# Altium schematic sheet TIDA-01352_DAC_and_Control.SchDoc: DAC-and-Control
size 431 x 279 mm; Date: Not shown in title block; ApprovedBy: Not shown in title block; CheckedBy: Not shown in title block; Author: Not shown in title block; CompanyName: Not shown in title block; DrawnBy: Sanjay Pithadia; Engineer: Not shown in title block; Organization: Not shown in title block; Address1: Not shown in title block; Address2: Not shown in title block; Address3: Not shown in title block; Address4: Not shown in title block; DocumentNumber: 1; Revision: Use project parameter SCH_Rev; SheetNumber: 5; SheetTotal: 9; PageSetup: Record=PageOptions¦CenterHorizontal=True¦CenterVertical=True¦PrintScale=1.00¦XCorrection=1.00¦YCorrection=1.00¦PrintKind=0¦BorderSize=5000000¦LeftOffset=0¦BottomOffset=0¦Orientation=2¦PaperLength=1000¦PaperWidth=1000¦Scale=100¦PaperSource=15¦PrintQuality=600¦MediaType=1¦DitherType=10¦PaperKind=Letter¦PrintScaleMode=1
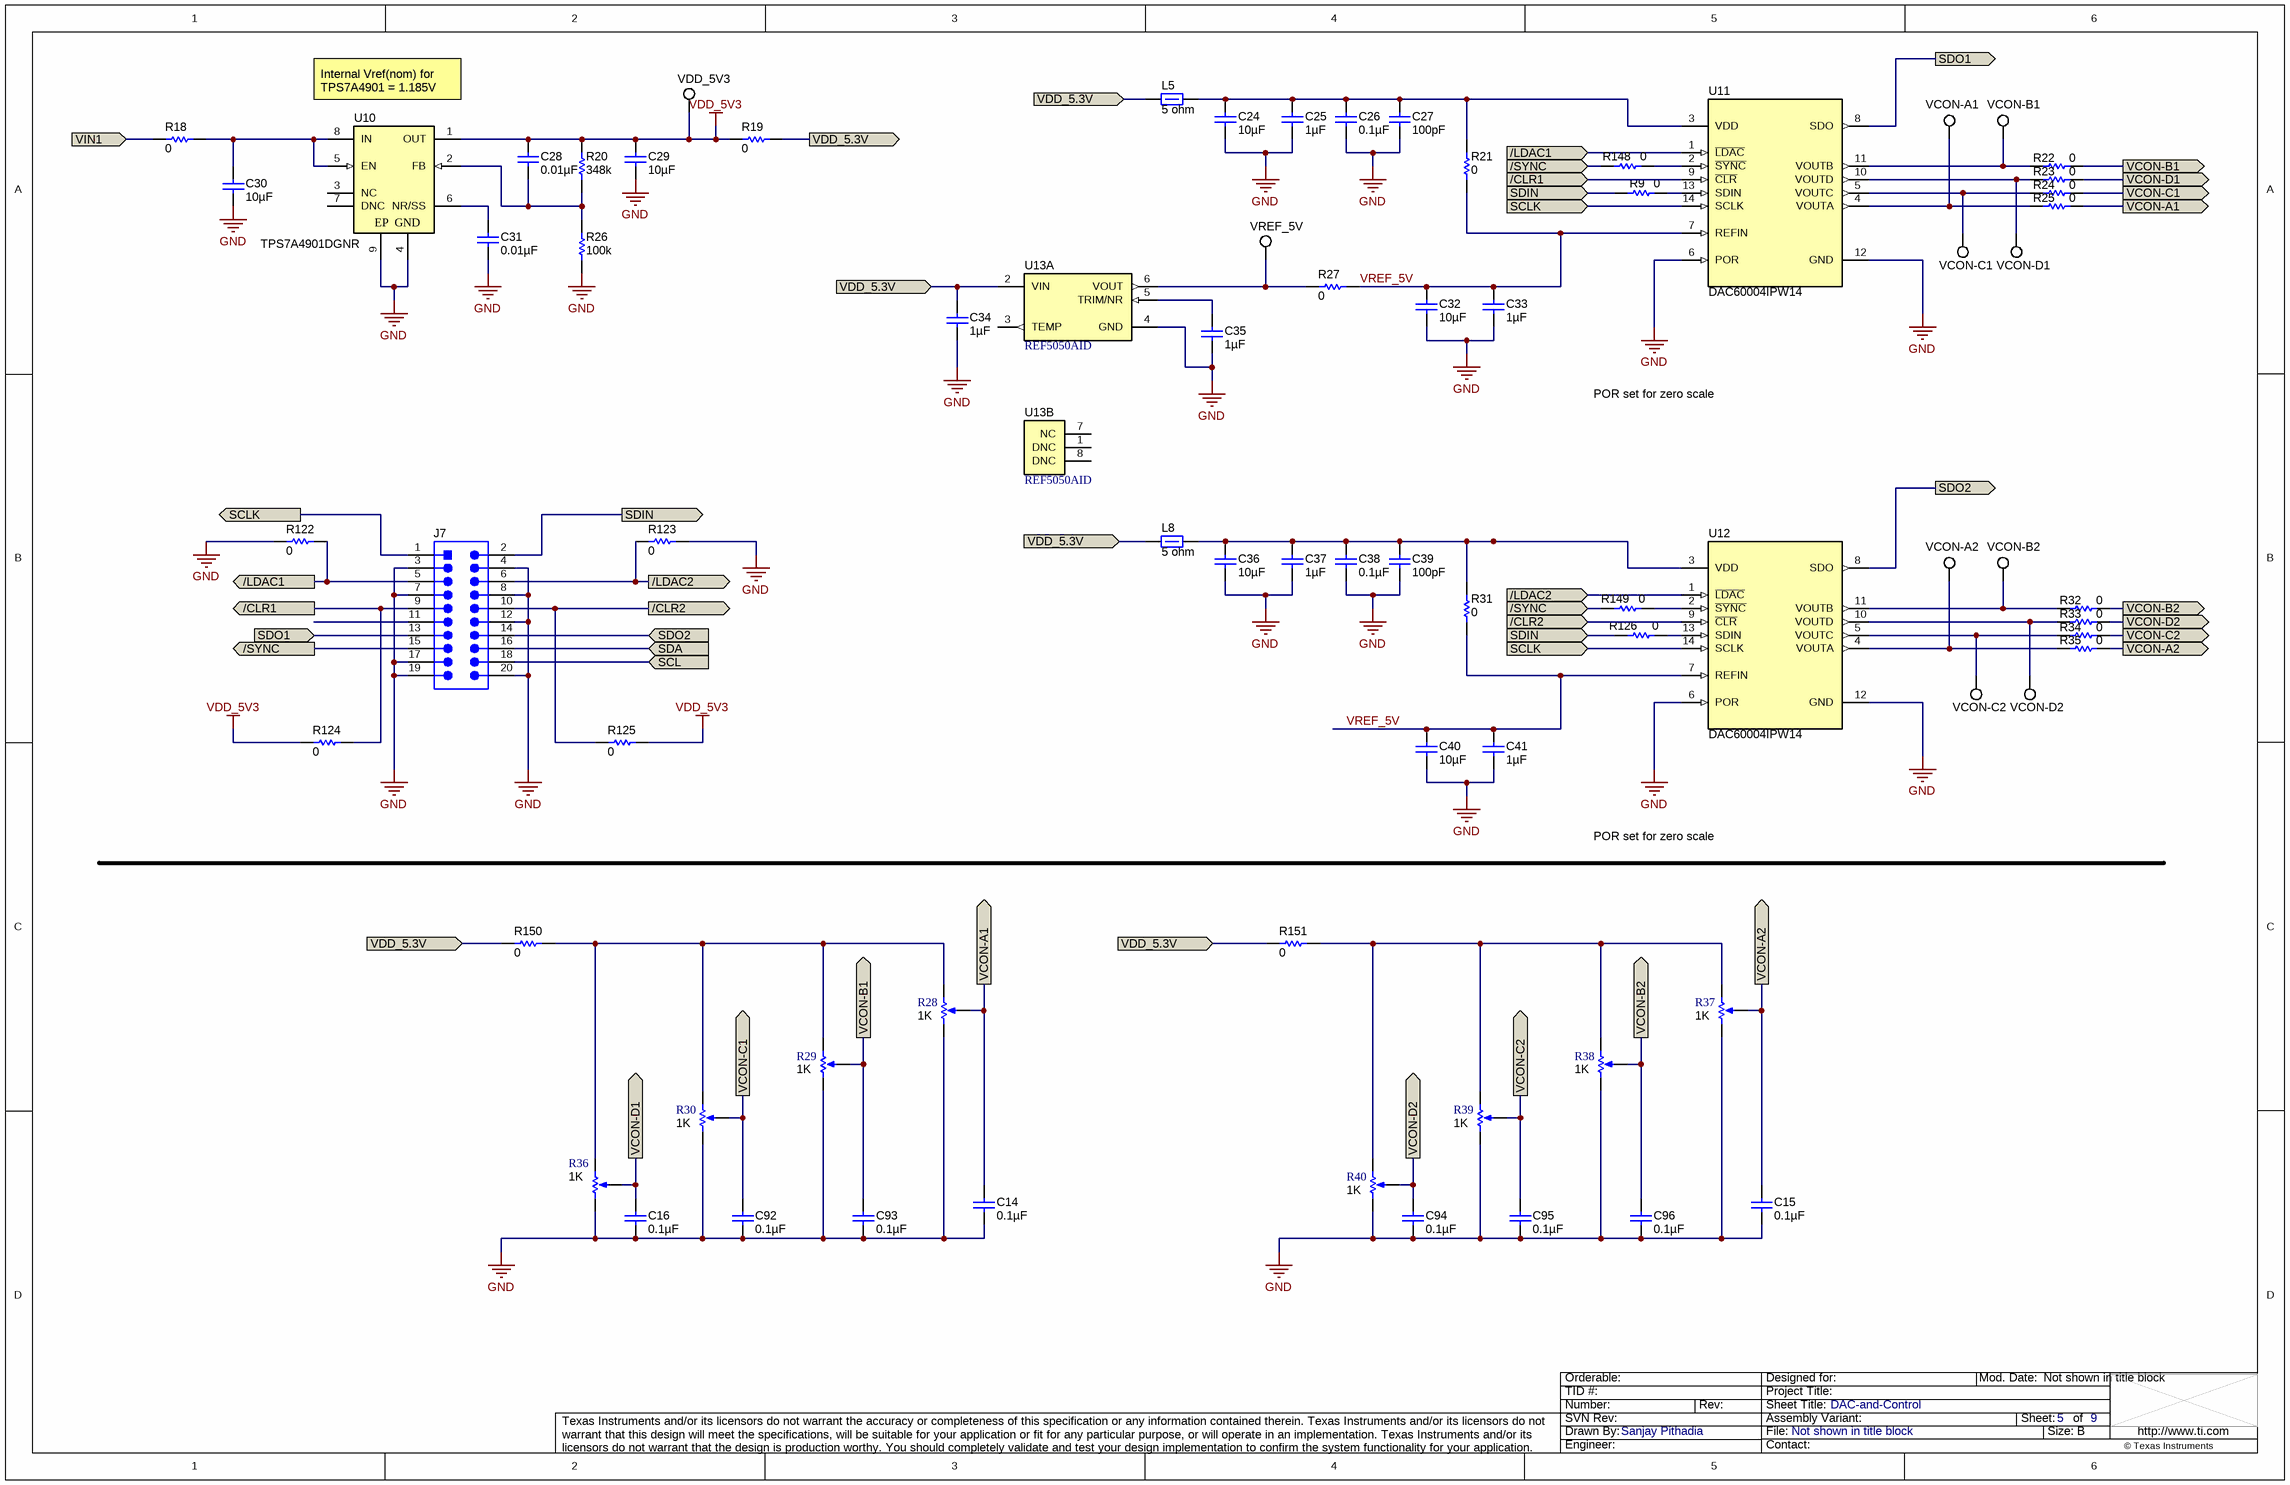
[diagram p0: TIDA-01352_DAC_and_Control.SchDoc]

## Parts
C14  ValueDisplayed: 0.1µF  [0603]  (hidden comment: 06033C104JAT2A)
C15  ValueDisplayed: 0.1µF  [0603]  (hidden comment: 06033C104JAT2A)
C16  ValueDisplayed: 0.1µF  [0603]  (hidden comment: 06033C104JAT2A)
C24  ValueDisplayed: 10µF  [0603]  (hidden comment: GRM188R61E106MA73D)
C25  ValueDisplayed: 1µF  [0603]  (hidden comment: C1608X5R1E105K080AC)
C26  ValueDisplayed: 0.1µF  [0603]  (hidden comment: C0603C104K5RACTU)
C27  ValueDisplayed: 100pF  [0603]  (hidden comment: GRM1885C1H101JA01D)
C28  ValueDisplayed: 0.01µF  [0603]  (hidden comment: GRM188R71H103KA01D)
C29  ValueDisplayed: 10µF  [1206_180]  (hidden comment: C3216X5R1H106K160AB)
C30  ValueDisplayed: 10µF  [1206_180]  (hidden comment: C3216X5R1H106K160AB)
C31  ValueDisplayed: 0.01µF  [0603]  (hidden comment: GRM188R71H103KA01D)
C32  ValueDisplayed: 10µF  [0603]  (hidden comment: GRM188R61E106MA73D)
C33  ValueDisplayed: 1µF  [0603]  (hidden comment: C1608X5R1E105K080AC)
C34  ValueDisplayed: 1µF  [0603]  (hidden comment: C1608X5R1E105K080AC)
C35  ValueDisplayed: 1µF  [0603]  (hidden comment: C1608X5R1E105K080AC)
C36  ValueDisplayed: 10µF  [0603]  (hidden comment: GRM188R61E106MA73D)
C37  ValueDisplayed: 1µF  [0603]  (hidden comment: C1608X5R1E105K080AC)
C38  ValueDisplayed: 0.1µF  [0603]  (hidden comment: C0603C104K5RACTU)
C39  ValueDisplayed: 100pF  [0603]  (hidden comment: GRM1885C1H101JA01D)
C40  ValueDisplayed: 10µF  [0603]  (hidden comment: GRM188R61E106MA73D)
C41  ValueDisplayed: 1µF  [0603]  (hidden comment: C1608X5R1E105K080AC)
C92  ValueDisplayed: 0.1µF  [0603]  (hidden comment: 06033C104JAT2A)
C93  ValueDisplayed: 0.1µF  [0603]  (hidden comment: 06033C104JAT2A)
C94  ValueDisplayed: 0.1µF  [0603]  (hidden comment: 06033C104JAT2A)
C95  ValueDisplayed: 0.1µF  [0603]  (hidden comment: 06033C104JAT2A)
C96  ValueDisplayed: 0.1µF  [0603]  (hidden comment: 06033C104JAT2A)
J7  PRPC010DAAN-RC  [Sullins_xxxC010DAAN]  (value not drawn)
L5  ValueDisplayed: 5 ohm  [0603]  (hidden comment: BLM18BB050SN1D)
L8  ValueDisplayed: 5 ohm  [0603]  (hidden comment: BLM18BB050SN1D)
R9  ValueDisplayed: 0  [0603]  (hidden comment: CRCW06030000Z0EA)
R18  ValueDisplayed: 0  [0603]  (hidden comment: CRCW06030000Z0EA)
R19  ValueDisplayed: 0  [0603]  (hidden comment: CRCW06030000Z0EA)
R20  ValueDisplayed: 348k  [0603]  (hidden comment: CRCW0603348KFKEA)
R21  ValueDisplayed: 0  [0603]  (hidden comment: CRCW06030000Z0EA)
R22  ValueDisplayed: 0  [0603]  (hidden comment: CRCW06030000Z0EA)
R23  ValueDisplayed: 0  [0603]  (hidden comment: CRCW06030000Z0EA)
R24  ValueDisplayed: 0  [0603]  (hidden comment: CRCW06030000Z0EA)
R25  ValueDisplayed: 0  [0603]  (hidden comment: CRCW06030000Z0EA)
R26  ValueDisplayed: 100k  [0603]  (hidden comment: RC0603FR-07100KL)
R27  ValueDisplayed: 0  [0603]  (hidden comment: CRCW06030000Z0EA)
R28  value 1K  [TRIM_3224X]  (hidden comment: 3224X-1-102E)
R29  value 1K  [TRIM_3224X]  (hidden comment: 3224X-1-102E)
R30  value 1K  [TRIM_3224X]  (hidden comment: 3224X-1-102E)
R31  ValueDisplayed: 0  [0603]  (hidden comment: CRCW06030000Z0EA)
R32  ValueDisplayed: 0  [0603]  (hidden comment: CRCW06030000Z0EA)
R33  ValueDisplayed: 0  [0603]  (hidden comment: CRCW06030000Z0EA)
R34  ValueDisplayed: 0  [0603]  (hidden comment: CRCW06030000Z0EA)
R35  ValueDisplayed: 0  [0603]  (hidden comment: CRCW06030000Z0EA)
R36  value 1K  [TRIM_3224X]  (hidden comment: 3224X-1-102E)
R37  value 1K  [TRIM_3224X]  (hidden comment: 3224X-1-102E)
R38  value 1K  [TRIM_3224X]  (hidden comment: 3224X-1-102E)
R39  value 1K  [TRIM_3224X]  (hidden comment: 3224X-1-102E)
R40  value 1K  [TRIM_3224X]  (hidden comment: 3224X-1-102E)
R122  ValueDisplayed: 0  [0603]  (hidden comment: CRCW06030000Z0EA)
R123  ValueDisplayed: 0  [0603]  (hidden comment: CRCW06030000Z0EA)
R124  ValueDisplayed: 0  [0603]  (hidden comment: CRCW06030000Z0EA)
R125  ValueDisplayed: 0  [0603]  (hidden comment: CRCW06030000Z0EA)
R126  ValueDisplayed: 0  [0603]  (hidden comment: CRCW06030000Z0EA)
R148  ValueDisplayed: 0  [0603]  (hidden comment: CRCW06030000Z0EA)
R149  ValueDisplayed: 0  [0603]  (hidden comment: CRCW06030000Z0EA)
R150  ValueDisplayed: 0  [0603]  (hidden comment: CRCW06030000Z0EA)
R151  ValueDisplayed: 0  [0603]  (hidden comment: CRCW06030000Z0EA)
U10  TPS7A4901DGNR  [DGN0008D_N]
U11  DAC60004IPW14  [PW0014A_N]
U12  DAC60004IPW14  [PW0014A_N]
U13  REF5050AID  [D0008A_N]  (parts A,B of 2)
VCON-A1  5002  [Keystone5002]  (value not drawn)
VCON-A2  5002  [Keystone5002]  (value not drawn)
VCON-B1  5002  [Keystone5002]  (value not drawn)
VCON-B2  5002  [Keystone5002]  (value not drawn)
VCON-C1  5002  [Keystone5002]  (value not drawn)
VCON-C2  5002  [Keystone5002]  (value not drawn)
VCON-D1  5002  [Keystone5002]  (value not drawn)
VCON-D2  5002  [Keystone5002]  (value not drawn)
VDD_5V3  5002  [Keystone5002]  (value not drawn)
VREF_5V  5002  [Keystone5002]  (value not drawn)

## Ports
/CLR1 (in), /CLR1 (out), /CLR2 (in), /CLR2 (out), /LDAC1 (in), /LDAC1 (out), /LDAC2 (in), /LDAC2 (out), /SYNC (in), /SYNC (out), SCL (in), SCLK (in), SCLK (out), SDA (in), SDIN (in), SDIN (out), SDO1 (in), SDO1 (out), SDO2 (in), SDO2 (out), VCON-A1 (out), VCON-A2 (out), VCON-B1 (out), VCON-B2 (out), VCON-C1 (out), VCON-C2 (out), VCON-D1 (out), VCON-D2 (out), VDD_5.3V (in), VDD_5.3V (out), VIN1 (in)

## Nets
GND: C14.2 C15.2 C16.2 C24.2 C25.2 C26.2 C27.2 C29.2 C30.2 C31.1 C32.2 C33.2 C34.2 C35.2 C36.2 C37.2 C38.2 C39.2 C40.2 C41.2 C92.2 C93.2 C94.2 C95.2 C96.2 J7.3 J7.4 J7.7 J7.8 J7.12 J7.17 J7.19 J7.20 R26.2 R28.1(CCW) R29.1(CCW) R30.1(CCW) R36.1(CCW) R37.1(CCW) R38.1(CCW) R39.1(CCW) R40.1(CCW) R122.2 R123.1 U10.4(GND) U10.9(EP) U11.6(POR) U11.12(GND) U12.6(POR) U12.12(GND) U13.4(GND)
VDD_5V3: C28.2 C29.1 R19.2 R20.1 R124.2 R125.1 U10.1(OUT) VDD_5V3.1
/CLR1: J7.9 R124.1 U11.9(~{CLR}) ; port /CLR1
/CLR2: J7.10 R125.2 U12.9(~{CLR}) ; port /CLR2
/LDAC1: J7.5 R122.1 U11.1(~{LDAC}) ; port /LDAC1
/LDAC2: J7.6 R123.2 U12.1(~{LDAC}) ; port /LDAC2
/SYNC: J7.15 R148.2 R149.2 ; port /SYNC
SCL: J7.18 ; port SCL
SCLK: J7.1 U11.14(SCLK) U12.14(SCLK) ; port SCLK
SDA: J7.16 ; port SDA
SDIN: J7.2 R9.2 R126.2 ; port SDIN
SDO1: J7.13 U11.8(SDO) ; port SDO1
SDO2: J7.14 U12.8(SDO) ; port SDO2
VCON-A1: C14.1 R25.1 R28.2(WIPER) ; port VCON-A1
VCON-A2: C15.1 R35.1 R37.2(WIPER) ; port VCON-A2
VCON-B1: C93.1 R22.1 R29.2(WIPER) ; port VCON-B1
VCON-B2: C96.1 R32.1 R38.2(WIPER) ; port VCON-B2
VCON-C1: C92.1 R24.1 R30.2(WIPER) ; port VCON-C1
VCON-C2: C95.1 R34.1 R39.2(WIPER) ; port VCON-C2
VCON-D1: C16.1 R23.1 R36.2(WIPER) ; port VCON-D1
VCON-D2: C94.1 R33.1 R40.2(WIPER) ; port VCON-D2
VDD_5.3V: C34.1 L5.1 L8.1 R19.1 R150.2 R151.2 U13.2(VIN) ; port VDD_5.3V
VIN1: R18.2 ; port VIN1
VREF_5V: C32.1 C33.1 C40.1 C41.1 R21.2 R27.1 R31.2 U11.7(REFIN) U12.7(REFIN)
NetC24_1: C24.1 C25.1 C26.1 C27.1 L5.2 R21.1 U11.3(VDD)
NetC28_1: C28.1 R20.2 R26.1 U10.2(FB)
NetC30_1: C30.1 R18.1 U10.5(EN) U10.8(IN)
NetC31_2: C31.2 U10.6(NR/SS)
NetC35_1: C35.1 U13.5(TRIM/NR)
NetC36_1: C36.1 C37.1 C38.1 C39.1 L8.2 R31.1 U12.3(VDD)
NetR9_1: R9.1 U11.13(SDIN)
NetR22_2: R22.2 U11.11(VOUTB) VCON-B1.1
NetR23_2: R23.2 U11.10(VOUTD) VCON-D1.1
NetR24_2: R24.2 U11.5(VOUTC) VCON-C1.1
NetR25_2: R25.2 U11.4(VOUTA) VCON-A1.1
NetR27_2: R27.2 U13.6(VOUT) VREF_5V.1
NetR28_3: R28.3(CW) R29.3(CW) R30.3(CW) R36.3(CW) R150.1
NetR32_2: R32.2 U12.11(VOUTB) VCON-B2.1
NetR33_2: R33.2 U12.10(VOUTD) VCON-D2.1
NetR34_2: R34.2 U12.5(VOUTC) VCON-C2.1
NetR35_2: R35.2 U12.4(VOUTA) VCON-A2.1
NetR37_3: R37.3(CW) R38.3(CW) R39.3(CW) R40.3(CW) R151.1
NetR126_1: R126.1 U12.13(SDIN)
NetR148_1: R148.1 U11.2(~{SYNC})
NetR149_1: R149.1 U12.2(~{SYNC})

Not connected (* = marked no-connect by the designer): J7 11; U10 3(NC) 7(DNC); U13 1(DNC) 3(TEMP) 7(NC) 8(DNC)

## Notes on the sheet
- (near U10) Internal Vref(nom) for TPS7A4901 = 1.185V
- POR set for zero scale

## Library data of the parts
C14-C16 C92-C96 = 06033C104JAT2A: CAP, CERM, 0.1 µF, 25 V, +/- 5%, X7R, 0603; Manufacturer: AVX; Polarized: N; CompType: Capacitor; Value: 0.1uF; U/M: EA; Cap_F: 0.0000001; Tolerance_%: 5; ESR_ohm: 0.05; Value1: 0.05 ohm; VDC_V: 25; Value2: 25V; TaMin_C: -55; TaMax_C: 125; SizeArea_mm2: 1.28; SizeAreaWB_mm2: 4.68; SizeX_mm: 1.6; SizeY_mm: 0.8; SizeZ_mm: 1; AEC Category: Q200
C24 C32 C36 C40 = GRM188R61E106MA73D: CAP, CERM, 10 µF, 25 V, +/- 20%, X5R, 0603; Manufacturer: MuRata; Polarized: N; CompType: Capacitor; Value: 10uF; U/M: EA; Cap_F: 0.00001; Tolerance_%: 20; Value1: Unknown; VDC_V: 25; Value2: 25V; TaMin_C: -55; TaMax_C: 85; SizeArea_mm2: 1.28; SizeAreaWB_mm2: 4.68; SizeX_mm: 1.6; SizeY_mm: 0.8; SizeZ_mm: 1; AEC Category: Q200
C25 C33-C35 C37 C41 = C1608X5R1E105K080AC: CAP, CERM, 1 µF, 25 V, +/- 10%, X5R, 0603; Manufacturer: TDK; Polarized: N; CompType: Capacitor; Value: 1uF; U/M: EA; Cap_F: 0.000001; Tolerance_%: 10; Value1: Unknown; VDC_V: 25; Value2: 25V; TaMin_C: -55; TaMax_C: 85; SizeArea_mm2: 1.28; SizeAreaWB_mm2: 4.68; SizeX_mm: 1.6; SizeY_mm: 0.8; SizeZ_mm: 1; AEC Category: Q200
C26 C38 = C0603C104K5RACTU: CAP, CERM, 0.1 µF, 50 V, +/- 10%, X7R, 0603; Manufacturer: Kemet; Polarized: N; CompType: Capacitor; Value: 0.1uF; U/M: EA; Cap_F: 0.0000001; Tolerance_%: 10; Value1: Unknown; VDC_V: 50; Value2: 50V; TaMin_C: -55; TaMax_C: 125; SizeArea_mm2: 1.28; SizeAreaWB_mm2: 4.68; SizeX_mm: 1.6; SizeY_mm: 0.8; SizeZ_mm: 1; AEC Category: Q200
C27 C39 = GRM1885C1H101JA01D: CAP, CERM, 100 pF, 50 V, +/- 5%, C0G/NP0, 0603; Manufacturer: MuRata; Polarized: N; CompType: Capacitor; Value: 100pF; U/M: EA; Cap_F: 0.0000000001; Tolerance_%: 5; Value1: Unknown; VDC_V: 50; Value2: 50V; TaMin_C: -55; TaMax_C: 125; SizeArea_mm2: 1.28; SizeAreaWB_mm2: 4.68; SizeX_mm: 1.6; SizeY_mm: 0.8; SizeZ_mm: 1; AEC Category: Q200
C28 C31 = GRM188R71H103KA01D: CAP, CERM, 0.01 µF, 50 V, +/- 10%, X7R, 0603; Manufacturer: MuRata; Polarized: N; CompType: Capacitor; Value: 0.01uF; U/M: EA; Cap_F: 0.00000001; Tolerance_%: 10; Value1: Unknown; VDC_V: 50; Value2: 50V; TaMin_C: -55; TaMax_C: 125; SizeArea_mm2: 1.28; SizeAreaWB_mm2: 4.68; SizeX_mm: 1.6; SizeY_mm: 0.8; SizeZ_mm: 1; AEC Category: Q200
C29 C30 = C3216X5R1H106K160AB: CAP, CERM, 10 µF, 50 V, +/- 10%, X5R, 1206; Manufacturer: TDK; Polarized: N; CompType: Capacitor; Value: 10uF; U/M: EA; Cap_F: 0.00001; Tolerance_%: 10; ESR_ohm: 0.002229; Value1: 0.002229 ohm; VDC_V: 50; Value2: 50V; IRMS_A: 4.85932; TaMin_C: -55; TaMax_C: 85; SizeArea_mm2: 5.12; SizeAreaWB_mm2: 10.92; SizeX_mm: 3.2; SizeY_mm: 1.6; SizeZ_mm: 1.8; AEC Category: Q200
J7 = PRPC010DAAN-RC: Header, 2.54mm, 10x2, Gold, TH; Manufacturer: Sullins Connector Solutions; SymbolCreator: a0412235; Pitch_mm: 2.54; Gender: Male; Shrouded: N; Row_Count: 2
L5 L8 = BLM18BB050SN1D: Ferrite Bead, 5 ohm @ 100 MHz, 0.7 A, 0603; Manufacturer: MuRata; Value: 5 ohm; Imax_A: 0.7; DCR_ohm: 0.05; Value1: 0.05 ohm; Value2: 0.7A; SizeAreaWB_mm2: 4.68; SizeArea_mm2: 1.28; SizeX_mm: 1.6; SizeY_mm: 0.8; SizeZ_mm: 1; ZTyp@100MHz_Ohm: 5
R9 R18 R19 R21-R25 R27 R31-R35 R122-R126 R148-R151 = CRCW06030000Z0EA: RES, 0, 5%, 0.1 W, 0603; Manufacturer: Vishay-Dale; CompType: Resistor; Value: 0; Value_Code: 0000; Tolerance_%: 5; Power_W: 0.1; Value2: 0.1W; VDC_V: 75; TempCo: 200 ppm/C; SizeArea_mm2: 1.28; SizeX_mm: 1.6; SizeY_mm: 0.8; SizeZ_mm: 1; EIA_Code: E24; U/M: EA; AEC Category: Q200
R20 = CRCW0603348KFKEA: RES, 348 k, 1%, 0.1 W, 0603; Manufacturer: Vishay-Dale; CompType: Resistor; Value: 348k; Res_ohm: 348000; Tolerance_%: 1; Power_W: 0.1; Value2: 0.1W; VDC_V: 75; TempCo: 100 ppm/C; SizeArea_mm2: 1.28; SizeX_mm: 1.6; SizeY_mm: 0.8; EIA_Code: E96; U/M: EA; AEC Category: Q200
R26 = RC0603FR-07100KL: RES, 100 k, 1%, 0.1 W, 0603; Manufacturer: Yageo America; CompType: Resistor; Value: 100k; Res_ohm: 100000; Tolerance_%: 1; Power_W: 0.1; Value2: 0.1W; VDC_V: 150; TempCo: 200 ppm/C; SizeArea_mm2: 1.28; SizeX_mm: 1.6; SizeY_mm: 0.8; EIA_Code: E96; U/M: EA; AEC Category: Q200
R28-R30 R36-R40 = 3224X-1-102E: Trimmer, 1 K, 0.25 W, SMD; Manufacturer: Bourns; Sim Note: Enter the Resistance value and the set point into parameter fields.; SymbolCreator: a0412235
U10 = TPS7A4901DGNR: Single Output High PSRR LDO, 150 mA, Adjustable 1.2 to 33 V Output, 3 to 36 V Input, with Ultra-Low Noise, 8-pin MSOP (DGN), -40 to 125 degC, Green (RoHS & no Sb/Br); Manufacturer: Texas Instruments; Alternate PartNumber: Equivalent; Accuracy(%): 1.5; Iout(Max)(A): 0.15; Iq(Typ)(mA): 0.06; Power Good: TRUE; SubFamily: Single Channel LDO; Vdo(Typ)(mV): 260; Vin(Max)(V): 36; Vin(Min)(V): 3; Vout Adj(Max)(V): 33; Vout Adj(Min)(V): 1.2
U11 U12 = DAC60004IPW14: QUAD 12-BIT, 1LSB INL, BUFFERED, VOLTAGE-OUTPUT DIGITAL-to-ANALOG CONVERTERS, PW0014A (TSSOP-14); Manufacturer: Texas Instruments; SymbolCreator: a0411947; SizeArea_mm2: 32; SizeAreaWB_mm2: 58.8; SizeX_mm: 6.4; SizeY_mm: 5; SizeZ_mm: 1.2; CompType: IC; U/M: EA
U13 = REF5050AID: Low Noise, Very Low Drift, Precision Voltage Reference, -40 to 125 degC, 8-pin SOIC (D), Green (RoHS & no Sb/Br); Manufacturer: Texas Instruments; Alternate PartNumber: Equivalent; Initial Accuracy @ 25/deg C(%): 0.05; Iout/Iz(Max)(mA): 10; Iq(Max)(uA): 1000; Rating: Catalog; SubFamily: Series Voltage Reference; Temp Coeff(Max)(ppm/ degree C): 3; VI(Max)(V): 18; VI(Min)(V): 5.2; VO(V): 5
VCON-A1 VCON-A2 VCON-B1 VCON-B2 VCON-C1 VCON-C2 VCON-D1 VCON-D2 VDD_5V3 VREF_5V = 5002: Test Point, Miniature, White, TH; Manufacturer: Keystone; CompType: Test Point Loop; ContactFinish: Silver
